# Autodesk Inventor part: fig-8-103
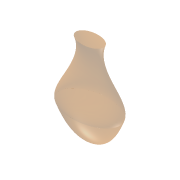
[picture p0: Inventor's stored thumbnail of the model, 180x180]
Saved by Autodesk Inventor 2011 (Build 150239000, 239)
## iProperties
Created: 2004-05
Part Number: fig-8-103
Document SubType Name: Modeling
Designer: CADCIM Technologies
Manufacturer: Standard
Standards Organization: Custom
Density: 1 g/cm^3
Author: CADCIM Technologies
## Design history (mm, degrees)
sketch "Sketch4"
  geometry: 1 further point; 1 other entity
  constraints: 2 other
workplane "Work Plane2"
sketch "Sketch5"
  geometry: 1 further point; 1 other entity
  constraints: 2 other
feature "LoftSrf1" sketch "Sketch5" dims "d4" = 20, "d5" = 110 deg, "d6" = 40, "d7" = 70 deg
patch "Boundary Patch2" dims "d10" = 0, "d11" = 0
patch "Boundary Patch3" dims "d13" = 0, "d14" = 0
body "Srf1"
body "Srf3"
body "Srf4"
other parameters: "d3" = 33.5
